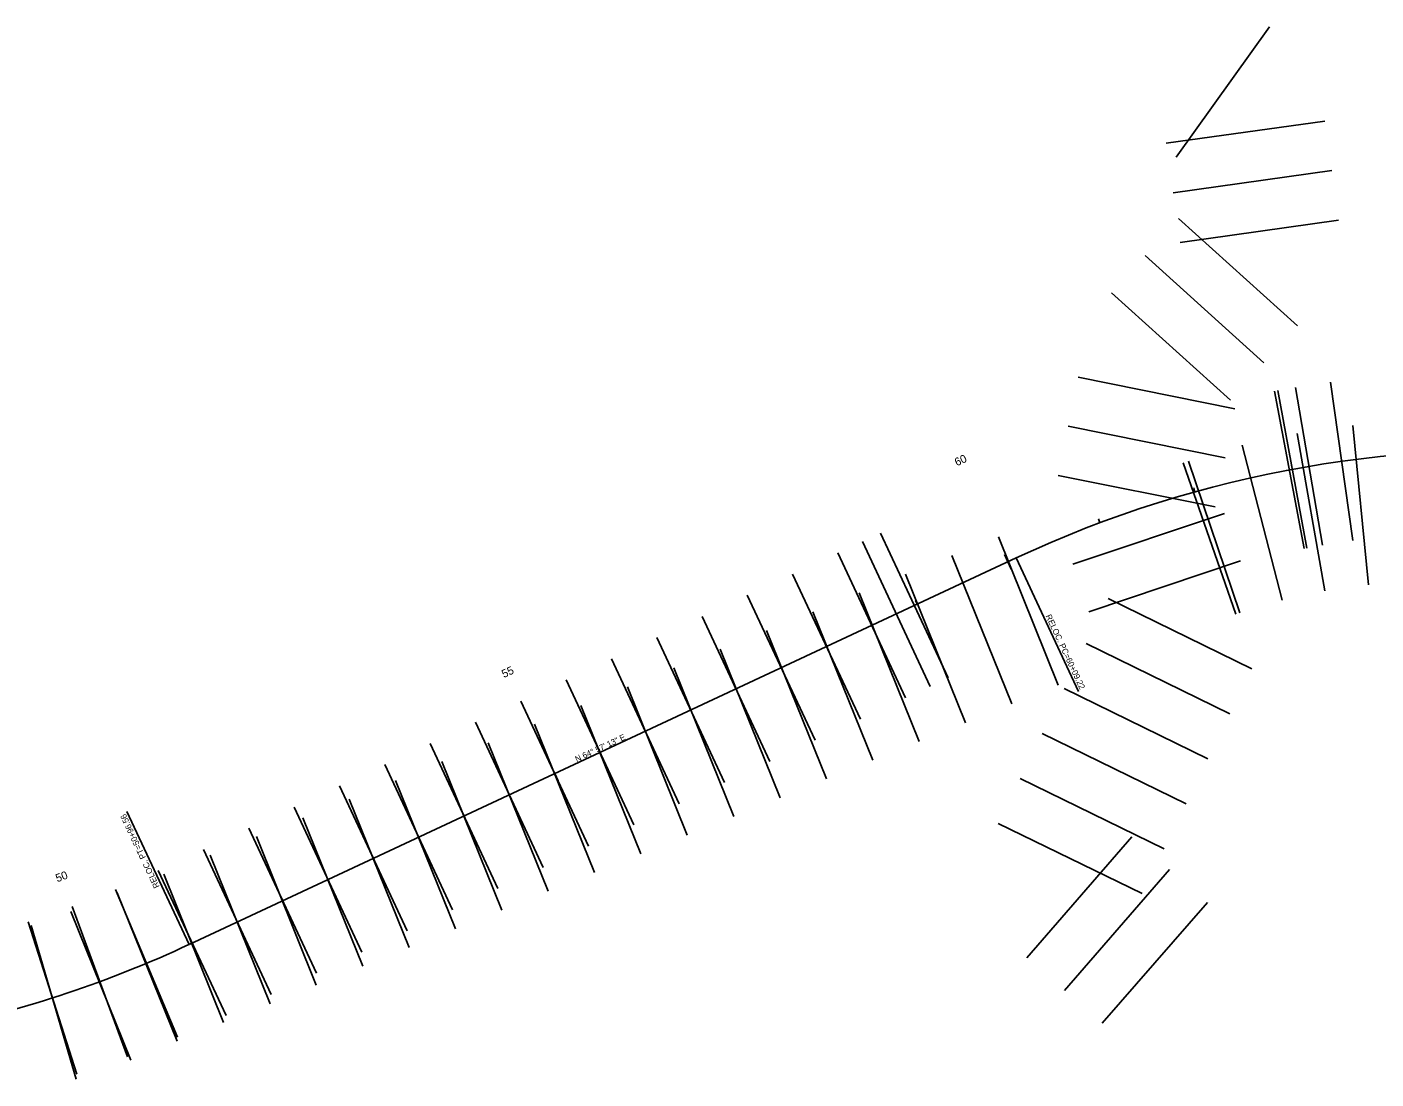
# Model space of a CAD drawing. Extents: x 1965757 to 1970272, y 1117058 to 1118406.
# Drawn here: x 1966697 to 1968046, y 1117355 to 1118406 of the extents above; entities that cross this region are included whole.
import ezdxf

# ---------------------------------------------------------------- set-up
doc = ezdxf.new("R2010")
doc.units = 0
for name, color, linetype in [('RD_HC_CL_Rel', 7, 'Continuous'), ('RD_HC_Data_Rel', 7, 'Continuous'), ('RD_HC_Data_Tic_Rel', 7, 'Continuous'), ('RD_HC_TX_Rel_Sta50', 7, 'Continuous'), ('RD_PD_PatLn1', 7, 'Continuous'), ('RD_PD_PatLn2', 7, 'Continuous'), ('RD_PD_PatLn3', 7, 'Continuous')]:
    doc.layers.add(name, color=color, linetype=linetype)

msp = doc.modelspace()

# ---------------------------------------------------------------- linework, layer by layer
at = {"layer": 'RD_HC_CL_Rel'}
msp.add_line((1966858.9, 1117489.3), (1967685.7, 1117875.7), dxfattribs=at)
for centre, start, end in [((1968170.8, 1116837.5), 84.6661, 115.0463), ((1966373.7, 1118527.5), 281.9047, 295.0463)]:
    msp.add_arc(centre, 1145.9, start, end, dxfattribs=at)
at = {"layer": 'RD_HC_Data_Rel'}
for p, q in [((1967685.7, 1117875.7), (1967748.1, 1117742.2)), ((1966858.9, 1117489.3), (1966796.7, 1117622.3))]:
    msp.add_line(p, q, dxfattribs=at)
at = {"layer": 'RD_HC_Data_Tic_Rel'}
for p, q in [((1967961.9, 1117964.2), (1967961.1, 1117968.1)), ((1967864.5, 1117941.7), (1967863.4, 1117945.6)), ((1967769.4, 1117910.8), (1967768, 1117914.6)), ((1967677.4, 1117871.8), (1967674, 1117879)), ((1967677.4, 1117871.8), (1967680.7, 1117864.5)), ((1967586.8, 1117829.4), (1967585.1, 1117833.1)), ((1967496.2, 1117787.1), (1967494.5, 1117790.7)), ((1967405.6, 1117744.8), (1967403.9, 1117748.4)), ((1967315, 1117702.4), (1967313.3, 1117706.1)), ((1967224.4, 1117660.1), (1967221, 1117667.3)), ((1967224.4, 1117660.1), (1967227.8, 1117652.8)), ((1967133.8, 1117617.8), (1967132.1, 1117621.4)), ((1967043.2, 1117575.4), (1967041.5, 1117579)), ((1966952.6, 1117533.1), (1966950.9, 1117536.7)), ((1966862, 1117490.8), (1966860.3, 1117494.4)), ((1966769.8, 1117452.2), (1966767, 1117459.7)), ((1966769.8, 1117452.2), (1966772.5, 1117444.6))]:
    msp.add_line(p, q, dxfattribs=at)
at = {"layer": 'RD_PD_PatLn1'}
for p, q in [((1968022.2, 1118007.9), (1968037.9, 1117848.7)), ((1967966.6, 1118000.2), (1967994.4, 1117842.7)), ((1967911.8, 1117988.4), (1967951.6, 1117833.4)), ((1967852.9, 1117970.6), (1967905.5, 1117819.5)), ((1967858, 1117972.3), (1967909.5, 1117820.9)), ((1967668, 1117896.8), (1967727.9, 1117748.5)), ((1967621.6, 1117878.1), (1967681.6, 1117729.8)), ((1967575.3, 1117859.4), (1967635.2, 1117711)), ((1967528.9, 1117840.7), (1967588.8, 1117692.3)), ((1967482.5, 1117821.9), (1967542.5, 1117673.6)), ((1967436.2, 1117803.2), (1967496.1, 1117654.8)), ((1967389.8, 1117784.5), (1967449.8, 1117636.1)), ((1967343.5, 1117765.7), (1967403.4, 1117617.4)), ((1967297.1, 1117747), (1967357, 1117598.7)), ((1967250.7, 1117728.3), (1967310.7, 1117579.9)), ((1967204.4, 1117709.6), (1967264.3, 1117561.2)), ((1967158, 1117690.8), (1967217.9, 1117542.5)), ((1967111.7, 1117672.1), (1967171.6, 1117523.8)), ((1967065.3, 1117653.4), (1967125.2, 1117505)), ((1967018.9, 1117634.7), (1967078.9, 1117486.3)), ((1966972.6, 1117615.9), (1967032.5, 1117467.6)), ((1966926.2, 1117597.2), (1966986.1, 1117448.8)), ((1966879.9, 1117578.5), (1966939.8, 1117430.1)), ((1966833.5, 1117559.7), (1966893.4, 1117411.4)), ((1966787.1, 1117541), (1966847.1, 1117392.7)), ((1966740.8, 1117522.3), (1966800.7, 1117373.9)), ((1966701, 1117508.4), (1966746.1, 1117354.9))]:
    msp.add_line(p, q, dxfattribs=at)
at = {"layer": 'RD_PD_PatLn2'}
for p, q in [((1968000.1, 1118051.5), (1968022.3, 1117893)), ((1967944.1, 1118042.3), (1967973.7, 1117885)), ((1967947.3, 1118042.9), (1967976.4, 1117885.6)), ((1967965.2, 1118046.1), (1967992, 1117888.3)), ((1967550.2, 1117900.6), (1967617.9, 1117755.7)), ((1967532, 1117892.2), (1967599.8, 1117747.2)), ((1967507.6, 1117880.7), (1967575.3, 1117735.8)), ((1967462.3, 1117859.6), (1967530, 1117714.6)), ((1967417, 1117838.4), (1967484.7, 1117693.5)), ((1967371.7, 1117817.2), (1967439.4, 1117672.3)), ((1967326.4, 1117796.1), (1967394.1, 1117651.1)), ((1967281.1, 1117774.9), (1967348.8, 1117630)), ((1967235.8, 1117753.7), (1967303.5, 1117608.8)), ((1967190.5, 1117732.6), (1967258.2, 1117587.6)), ((1967145.2, 1117711.4), (1967212.9, 1117566.4)), ((1967099.9, 1117690.2), (1967167.6, 1117545.3)), ((1967054.6, 1117669.1), (1967122.3, 1117524.1)), ((1967009.3, 1117647.9), (1967077, 1117502.9)), ((1966964, 1117626.7), (1967031.7, 1117481.8)), ((1966918.7, 1117605.6), (1966986.4, 1117460.6)), ((1966873.4, 1117584.4), (1966941.1, 1117439.4)), ((1966828.1, 1117563.2), (1966895.9, 1117418.3)), ((1966785.4, 1117544.2), (1966847.2, 1117396.7)), ((1966742.1, 1117527.2), (1966797.4, 1117377.1)), ((1966698.1, 1117512.1), (1966746.8, 1117359.7))]:
    msp.add_line(p, q, dxfattribs=at)
at = {"layer": 'RD_PD_PatLn3'}
for p, q in [((1967938.9, 1118406.3), (1967845.9, 1118276.1)), ((1967994.3, 1118312.3), (1967835.9, 1118290.1)), ((1968001.3, 1118262.8), (1967842.8, 1118240.5)), ((1967966.9, 1118107.8), (1967848, 1118214.9)), ((1968008.2, 1118213.3), (1967849.8, 1118191)), ((1967933.4, 1118070.7), (1967814.6, 1118177.8)), ((1967899.9, 1118033.5), (1967781.1, 1118140.7)), ((1967904.5, 1118024.6), (1967747.6, 1118056.2)), ((1967894.6, 1117975.6), (1967737.8, 1118007.2)), ((1967884.7, 1117926.6), (1967727.9, 1117958.2)), ((1967894.1, 1117920.1), (1967742.4, 1117869.3)), ((1967910, 1117872.7), (1967758.3, 1117821.9)), ((1967921.4, 1117764.8), (1967777.6, 1117835)), ((1967899.5, 1117719.9), (1967755.7, 1117790.1)), ((1967877.5, 1117675), (1967733.7, 1117745.1)), ((1967855.6, 1117630), (1967711.8, 1117700.2)), ((1967833.7, 1117585.1), (1967689.9, 1117655.3)), ((1967811.7, 1117540.2), (1967667.9, 1117610.3)), ((1967801.4, 1117597), (1967696.4, 1117476.2)), ((1967839.1, 1117564.2), (1967734.2, 1117443.4)), ((1967876.9, 1117531.4), (1967771.9, 1117410.6))]:
    msp.add_line(p, q, dxfattribs=at)

# ---------------------------------------------------------------- texts
at = {"layer": 'RD_HC_Data_Rel'}
for s, rotation, p in [('RELOC. PC=60+09.22', 295.0463, (1967715, 1117817.6)), ('N 64%%d 57\' 13" E', 25.0463, (1967246.5, 1117671.5)), ('RELOC. PT=50+96.56', 115.0463, (1966829.5, 1117547.3))]:
    msp.add_text(s, height=6, rotation=rotation, dxfattribs=at).set_placement(p)
at = {"layer": 'RD_HC_TX_Rel_Sta50'}
for s, rotation, p in [('60', 25.0463, (1967626.5, 1117967.2)), ('55', 25.0463, (1967173.7, 1117755.6)), ('50', 20.2184, (1966727.2, 1117551.5))]:
    msp.add_text(s, height=8, rotation=rotation, dxfattribs=at).set_placement(p)

doc.saveas('drawing.dxf')
